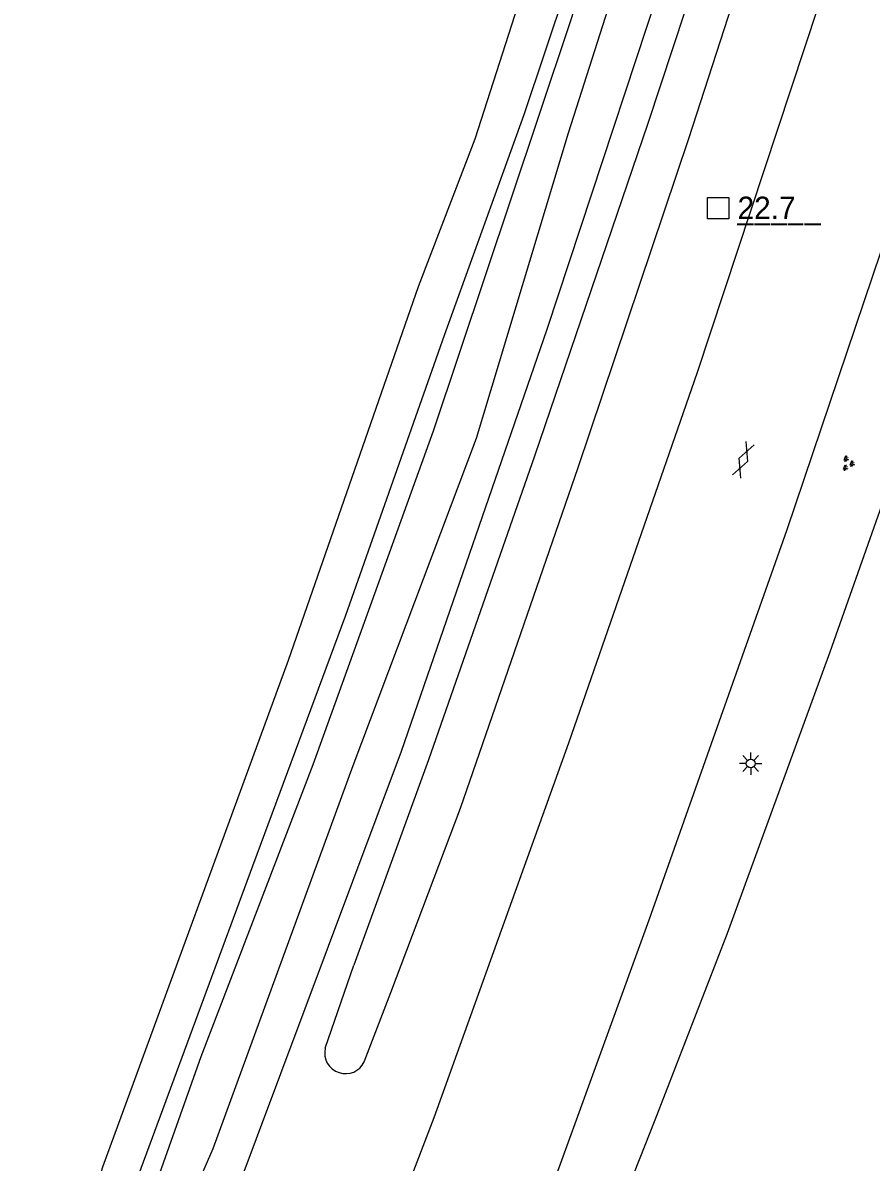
# Model space of a CAD drawing. Extents: x 125000 to 129004, y 397500 to 399008.
# Drawn here: x 125927.9 to 125975.4, y 397759.4 to 397823.1 of the extents above; entities that cross this region are included whole.
import ezdxf

# ---------------------------------------------------------------- set-up
doc = ezdxf.new("R2010")
doc.units = 0
for name, color, linetype in [('gg-afsc-hekwerk', 7, 'Continuous'), ('gg-knt-verharding', 7, 'Continuous'), ('gg-kntw-greppel-droge sloot', 7, 'Continuous'), ('gt-anno-nummer hm paal', 7, 'Continuous'), ('gt-symb-gesloten verharding', 7, 'Continuous'), ('gt-symb-groenvak', 7, 'Continuous'), ('gt-symb-hm paal', 7, 'Continuous'), ('gt-symb-lichtmast', 7, 'Continuous'), ('gx-grn-maaiveld', 7, 'Continuous')]:
    doc.layers.add(name, color=color, linetype=linetype)

# ---------------------------------------------------------------- blocks, each defined once
blk = doc.blocks.new('gt0-GRVAK')
at = {"layer": 'gt-symb-groenvak'}
for p, q in [((-0.11, 0.189), (-0.228, 0.24)), ((-0.182, 0.153), (0.088, 0.153)), ((-0.091, 0.211), (-0.156, 0.322)), ((-0.047, 0.214), (-0.047, 0.393)), ((-0.004, 0.211), (0.061, 0.322)), ((0.015, 0.189), (0.133, 0.24)), ((0.262, -0.052), (0.197, 0.059)), ((0.305, -0.049), (0.305, 0.13)), ((0.349, -0.052), (0.414, 0.059)), ((-0.245, -0.228), (-0.363, -0.177)), ((-0.318, -0.264), (-0.047, -0.264)), ((-0.226, -0.206), (-0.291, -0.095)), ((-0.183, -0.203), (-0.183, -0.024)), ((-0.139, -0.206), (-0.074, -0.095)), ((-0.12, -0.228), (-0.002, -0.177)), ((0.243, -0.074), (0.125, -0.023)), ((0.17, -0.11), (0.441, -0.11)), ((0.368, -0.074), (0.486, -0.023))]:
    blk.add_line(p, q, dxfattribs=at)
blk = doc.blocks.new('gt0-GESVH1')
at = {"layer": 'gt-symb-gesloten verharding'}
for p, q in [((-0.992, -0.261), (0.008, 0.239)), ((0.008, -0.261), (-0.992, 0.239)), ((0.008, 0.239), (1.008, -0.261)), ((1.008, 0.239), (0.008, -0.261))]:
    blk.add_line(p, q, dxfattribs=at)
blk = doc.blocks.new('gt0-HMpaal')
at = {"layer": 'gt-symb-hm paal'}
blk.add_lwpolyline([(-0.6, 0.6), (0.6, 0.6), (0.6, -0.6), (-0.6, -0.6)], close=True, dxfattribs=at)
blk = doc.blocks.new('gt0-LMAST')
at = {"layer": 'gt-symb-lichtmast'}
for p, q in [((-0.182, 0.173), (-0.447, 0.438)), ((-0.005, 0.246), (-0.005, 0.621)), ((0.172, 0.173), (0.437, 0.438)), ((-0.255, -0.004), (-0.63, -0.004)), ((-0.182, -0.181), (-0.447, -0.446)), ((-0.005, -0.254), (-0.005, -0.629)), ((0.437, -0.446), (0.172, -0.181)), ((0.245, -0.004), (0.62, -0.004))]:
    blk.add_line(p, q, dxfattribs=at)
blk.add_circle((-0.005, -0.004), 0.25, dxfattribs=at)

msp = doc.modelspace()

# ---------------------------------------------------------------- linework, layer by layer
at = {"layer": 'gg-afsc-hekwerk'}
msp.add_lwpolyline([(125939.62, 397757.065), (125949.099, 397782.385), (125957.248, 397805.988), (125965.331, 397830.483)], dxfattribs=at)
at = {"layer": 'gg-knt-verharding'}
for points in [[(125951.651, 397732.776), (125957.754, 397747.727), (125963.305, 397761.742), (125967.355, 397772.2), (125973.103, 397787.938), (125978.456, 397803.105), (125983.884, 397818.87), (125985.646, 397824.556), (125990.901, 397842.196), (125995.346, 397857.001)], [(125929.739, 397708.575), (125935.593, 397722.991), (125941.156, 397736.899), (125943.448, 397742.856), (125943.614, 397742.815), (125950.926, 397761.883), (125958.477, 397782.842), (125965.681, 397803.592), (125972.441, 397824.011), (125978.36, 397842.893), (125982.424, 397856.143)], [(125989.219, 397852.439), (125977.378, 397814.594), (125970.684, 397794.758), (125962.951, 397772.926), (125955.882, 397753.468), (125947.324, 397731.546), (125940.274, 397713.873), (125935.797, 397703.204)]]:
    msp.add_lwpolyline(points, dxfattribs=at)
at = {"layer": 'gg-kntw-greppel-droge sloot'}
for p, q in [((125944.831, 397765.758), (125946.431, 397770.404)), ((125947.002, 397764.99), (125948.499, 397768.881))]:
    msp.add_line(p, q, dxfattribs=at)
for points in [[(125972.496, 397848.098), (125967.759, 397832.265), (125962.899, 397817.51), (125956.554, 397798.893), (125950.604, 397781.899), (125946.431, 397770.404)], [(125948.499, 397768.881), (125952.408, 397779.19), (125958.985, 397798.261), (125965.187, 397816.662), (125970.714, 397833.712), (125974.616, 397846.56)]]:
    msp.add_lwpolyline(points, dxfattribs=at)
for centre, radius, start, end in [((125945.914, 397765.477), 1.119, 165.4821, 254.32521), ((125945.987, 397765.449), 1.114, 250.34486, 335.65375)]:
    msp.add_arc(centre, radius, start, end, dxfattribs=at)
at = {"layer": 'gx-grn-maaiveld'}
for points in [[(125959.751, 397861.626), (125961.296, 397858.649), (125962.608, 397855.907), (125963.462, 397852.811), (125964.142, 397849.957), (125964.783, 397846.624), (125964.977, 397844.465), (125964.847, 397841.747), (125964.797, 397839.572), (125964.614, 397837.729), (125963.458, 397832.66), (125958.432, 397816.97), (125953.281, 397799.876), (125946.365, 397781.561), (125938.529, 397760.128), (125934.218, 397750.235), (125933.763, 397749.483), (125933.176, 397748.977), (125899.468, 397733.352), (125869.337, 397719.293), (125865.978, 397717.556), (125864.331, 397717.722), (125862.945, 397718.409), (125854.67, 397737.606)], [(125958.92, 397859.399), (125959.942, 397856.907), (125962.103, 397850.367), (125962.92, 397845.94), (125963.157, 397842.495), (125963.087, 397840.157), (125962.674, 397837.157), (125962.059, 397834.467), (125958.623, 397823.42), (125956.731, 397817.783), (125950.865, 397800.278), (125944.135, 397781.617), (125937.863, 397765.274), (125933.432, 397752.79), (125932.806, 397751.882), (125931.998, 397750.988), (125923.383, 397747.195), (125889.777, 397731.618), (125866.272, 397720.751), (125865.142, 397720.844), (125864.933, 397721.114), (125864.14, 397722.119), (125852.909, 397746.741)], [(125856.813, 397745.333), (125865.308, 397726.667), (125866.406, 397724.681), (125867.995, 397724.532), (125872.578, 397726.894), (125919.72, 397748.661), (125930.37, 397754.054), (125931.148, 397755.122), (125932.375, 397759.118), (125942.777, 397787.47), (125950.044, 397808.389), (125953.23, 397816.641), (125958.195, 397832.083), (125959.89, 397838.151)], [(125854.784, 397745.823), (125864.586, 397722.978), (125865.529, 397722.196), (125866.65, 397722.003), (125900.36, 397737.774), (125931.067, 397751.947), (125931.816, 397752.507), (125932.546, 397753.694), (125940.776, 397775.957), (125945.984, 397789.986), (125951.503, 397805.661), (125955.974, 397818.014), (125959.537, 397828.663), (125961.484, 397834.834)], [(125939.62, 397757.065), (125949.099, 397782.385), (125957.248, 397805.988), (125965.331, 397830.483)]]:
    msp.add_lwpolyline(points, dxfattribs=at)

# ---------------------------------------------------------------- block references
at = {"layer": 'gt-symb-gesloten verharding', "rotation": -111.76950168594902}
msp.add_blockref('gt0-GESVH1', (125968.257, 397798.686), dxfattribs=at)
at = {"layer": 'gt-symb-groenvak', "rotation": -111.76950168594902}
msp.add_blockref('gt0-GRVAK', (125974.091, 397798.509), dxfattribs=at)
at = {"layer": 'gt-symb-hm paal'}
msp.add_blockref('gt0-HMpaal', (125966.835, 397812.764), dxfattribs=at)
at = {"layer": 'gt-symb-lichtmast'}
msp.add_blockref('gt0-LMAST', (125968.662, 397781.693), dxfattribs=at)

# ---------------------------------------------------------------- texts
at = {"layer": 'gt-anno-nummer hm paal'}
msp.add_text('22.7', height=1.25, dxfattribs=at).set_placement((125967.916, 397812.16))
at = {"layer": 'gt-symb-hm paal'}
msp.add_text('_____', height=1.25, dxfattribs=at).set_placement((125967.916, 397812.16))

doc.saveas('drawing.dxf')
